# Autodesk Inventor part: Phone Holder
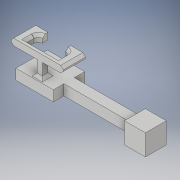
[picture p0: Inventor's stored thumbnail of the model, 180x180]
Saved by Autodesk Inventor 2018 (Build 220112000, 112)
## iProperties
Created: 2017-07
Part Number: Phone Holder
Material: Generic
Document SubType Name: Modeling
Designer: 17046589
Density: 1 g/cm^3
Appearance: Default
Author: 17046589
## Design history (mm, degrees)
sketch "Sketch1"
  geometry: L1 (0, 0)-(-10, 0); L2 (-10, 0)-(-10, -10); L3 (-10, -10)-(0, -10); L4 (0, -10)-(0, 0)
  constraints: 8 end point, 3 perpendicular, 1 horizontal
  dimensions: "d0" = 10 distance of L1.start L1.end; "d1" = 10 distance of L1.end L2.end
extrude "Extrusion1" new body sketch "Sketch1" distance "d2" = 10; taper "d3" = 0 deg
sketch "Sketch2"
  geometry: L1 (1.852, 7.705)-(1.852, 2.662); L2 (1.852, 2.662)-(6.852, 2.662); L3 (6.852, 2.662)-(6.852, 7.705); L4 (6.852, 7.705)-(1.852, 7.705); 1 further point
  constraints: 8 end point, 3 perpendicular, 1 vertical
  dimensions: "d4" = 5 distance of L1.end L2.end
extrude "Extrusion2" join sketch "Sketch2" distance "d5" = 30; taper "d6" = 0 deg
sketch "Sketch3"
  geometry: L1 (1.852, 7.705)-(1.852, 2.662) reference; L2 (1.852, 7.705)-(1.852, 2.662); L3 (1.852, 2.662)-(6.852, 2.662); L4 (6.852, 2.662)-(6.852, 7.705); L5 (6.852, 7.705)-(1.852, 7.705) reference; L6 (6.852, 7.705)-(1.852, 7.705); 1 further point
  constraints: 8 end point, 3 perpendicular, 1 collinear
extrude "Extrusion3" join sketch "Sketch3" distance "d7" = 20; taper "d8" = 0 deg
sketch "Sketch4"
  geometry: L1 (0, 5.043)-(50, 5.043) reference; L2 (32.103, 5.043)-(32.103, 0); L3 (0, 0)-(50, 0) reference; L4 (50, 0)-(50, 5.043) reference; L5 (50, 0)-(50, 5.043); L6 (50, 5.043)-(32.103, 5.043); 1 further point
  constraints: 6 end point, 2 point on line, 1 collinear, 1 perpendicular, 1 vertical
extrude "Extrusion4" join sketch "Sketch4" distance "d9" = 5; taper "d11" = 0 deg; dims "d10" = 10, "d12" = 0
sketch "Sketch5"
  geometry: L1 (-39.223, -3.148)-(-39.223, -0.537); L2 (-39.223, -0.537)-(-41.653, -0.537); L3 (-41.653, -0.537)-(-41.653, -3.148); L4 (-41.653, -3.148)-(-39.223, -3.148); 1 further point
  constraints: 8 end point, 3 perpendicular, 1 vertical
extrude "Extrusion5" join sketch "Sketch5" distance "d13" = 10; taper "d14" = 0 deg
sketch "Sketch6"
  geometry: L1 (0, 6.841)-(2.611, 6.841); L2 (2.611, 0)-(2.611, 10) reference; L3 (0, 10)-(2.611, 10) reference; L4 (2.611, 10)-(0, 10); L5 (0, 10)-(0, 6.841); 1 further point
  constraints: 6 end point, 1 collinear, 1 horizontal, 1 perpendicular, 1 point on line
extrude "Extrusion6" join sketch "Sketch6" distance "d15" = 10; taper "d17" = 0 deg; dims "d16" = 15, "d18" = 0
sketch "Sketch7"
  geometry: L1 (15, 10)-(-10, 10) reference; L2 (0, 6.841)-(-10, 6.841) reference; L3 (-10, 10)-(-10, 6.841); L4 (-10, 6.841)-(-5, 6.841); L5 (-5, 6.841)-(-5, 10); L6 (-5, 10)-(-10, 10); L7 (2.43, 6.841)-(15, 6.841) reference; L8 (15, 6.841)-(10, 6.841); L9 (10, 6.841)-(10, 10); L10 (10, 10)-(15, 10); L11 (15, 10)-(15, 6.841); 1 further point
  constraints: 16 end point, 4 perpendicular, 3 point on line, 1 midpoint, 1 vertical
  dimensions: "d19" = 5 distance of L2.end L4.end (derived); "d20" = 5 distance of L7.end L8.end
extrude "Extrusion7" join sketch "Sketch7" distance "d21" = 8; taper "d22" = 0 deg
sketch "Sketch8"
  geometry: L1 (0, 3.159)-(-8, 3.159) reference; L2 (-8, 3.159)-(-5.5, 3.159); L3 (-5.5, 3.159)-(-5.5, 0); L4 (0, 0)-(-8, 0) reference; L5 (-8, 0)-(-8, 3.159) reference; L6 (-8, 0)-(-8, 3.159); 1 further point
  constraints: 6 end point, 1 collinear, 1 horizontal, 1 perpendicular, 1 point on line
  dimensions: "d23" = 2.5 distance of L1.end L2.end
extrude "Extrusion8" join sketch "Sketch8" distance "d24" = 2; taper "d25" = 0 deg
sketch "Sketch9"
  geometry: L1 (0, 0)-(8, 0) reference; L2 (8, 3.159)-(8, 0) reference; L3 (8, 0)-(8, 3.159); L4 (8, 3.159)-(5.5, 3.159); L5 (0, 3.159)-(8, 3.159) reference; L6 (5.5, 3.159)-(5.255, 0); L7 (5.255, 0)-(8, 0); 1 further point
  constraints: 8 end point, 1 collinear, 1 perpendicular, 1 point on line
  dimensions: "d26" = 2.5 distance of L2.start L4.end
extrude "Extrusion9" join sketch "Sketch9" distance "d27" = 2; taper "d28" = 0 deg
fillet "Fillet1" dims "d29" = 2
fillet "Fillet2" dims "d30" = 2
chamfer "Chamfer1" distance "d31" = 1.25; stored, may be unused: second distance "d32" = 1.25, angle "d33" = 45 deg
chamfer "Chamfer2" distance "d34" = 1.25; stored, may be unused: second distance "d35" = 1.25, angle "d36" = 45 deg
chamfer "Chamfer3" distance "d37" = 1.25; stored, may be unused: second distance "d38" = 1.25, angle "d39" = 45 deg
chamfer "Chamfer4" distance "d40" = 1.25; stored, may be unused: second distance "d41" = 1.25, angle "d42" = 45 deg
chamfer "Chamfer5" distance "d43" = 1.25; stored, may be unused: second distance "d44" = 1.25, angle "d45" = 45 deg
chamfer "Chamfer6" distance "d46" = 1.25; stored, may be unused: second distance "d47" = 1.25, angle "d48" = 45 deg
chamfer "Chamfer7" distance "d49" = 1.25; stored, may be unused: second distance "d50" = 1.25, angle "d51" = 45 deg
chamfer "Chamfer8" distance "d52" = 1.25; stored, may be unused: second distance "d53" = 1.25, angle "d54" = 45 deg
chamfer "Chamfer9" distance "d55" = 1.25; stored, may be unused: second distance "d56" = 1.25, angle "d57" = 45 deg
chamfer "Chamfer10" distance "d58" = 1.25; stored, may be unused: second distance "d59" = 1.25, angle "d60" = 45 deg
body "Solid1"
